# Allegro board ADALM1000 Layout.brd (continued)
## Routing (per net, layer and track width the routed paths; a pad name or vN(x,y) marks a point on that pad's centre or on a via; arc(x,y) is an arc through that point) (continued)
6V0: length 48.7
  TOP w0.254: C41.2 42.86,37.13 U8.8
  TOP w0.305: v1(74.96,13.85) 74.71,13.6 D10.2 ; 71.09,5.47 71.03,5.41 UB11.11 ; 66,32.57 C77.2 ; C77.2 66,33.74 ; C77.2 66.55,33.15 ; 45.88,50.17 45.62,50.43 U6.2 U6.1 ; C54.2 41.8,43 C76.1 v1(41.44,41.66) ; C54.2 42.83,42.46 ; C54.2 42.86,42.97 A3.8 ; C47.1 41.67,37.16 C41.2 ; U6.1 45.05,49.36 ; U6.1 46,49.93 ; D10.5 74.71,15.5 v1(74.46,15.76) ; R97.1 46.77,47.89 46.52,47.63 46.01,47.63
  TOP w0.33: UA11.11 68.94,40.85
  TOP w0.356: 46.68,17.28 46.56,17.15 B3.8
  TOP w0.381: D7.5 v1(74.96,39.12) ; D7.2 v1(74.96,42.81)
  TOP w0.508: v1(69.21,42.84) C68.1 C46.2 70.08,40.85 68.94,40.85 ; C47.1 41.44,36.15 ; v1(67.47,22.49) 66.46,22.49 ; 66.46,22.49 66.33,22.36 66.33,20.84 B4.8 ; 66.46,22.49 65.69,22.49 64.8,23.38 C82.1 64.3,23.06 v1(64.3,21.98) ; 66.07,32.24 A4.8 67.47,31.63 ; 45.74,47.89 C106.1 45.06,48.64 ; 46.68,17.28 47.2,17.8 C79.2 48.08,17.8 C80.1 v1(48.45,19.31) ; C41.2 v1(42.83,36.46) ; 71.09,5.47 71.79,5.47 71.79,6.9 C62.1 v1(71.12,7.28)
  TOP w0.635: 67.14,35.31 C78.1 66.37,34.33
  TOP w0.762: v1(48.42,51.7) v1(48.42,52.59) 48.66,52.34 D3.A
  vias: v1(41.44,35.95) v1(42.2,41.66) v1(42.2,35.95) v1(42.83,42.17) v1(46.01,48.52) v1(46.01,47.76) v1(65.95,34.04) v1(66.71,34.04)
6V5: length 33.1
  TOP w0.254: R18.1 27.97,33.03 28.61,32.39 32.93,32.39 33.69,33.15
  TOP w0.635: E4.1 39.79,45.79 39.79,33.79 39.15,33.15
  TOP w0.762: L4.2 38.19,39.25 ; L4.2 36.99,38.44 ; L4.2 34.83,39.25 C45.1
  TOP w1.016: C29.1 35.42,35.06 ; C29.1 C45.1 ; C29.1 34.32,33.41
-1V0: length 41.9
  TOP w0.305: v1(48.42,39.76) 48.42,39.25 48.59,39.08 U8.4 49.12,39.08 49.25,39.21 v1(49.25,39.76) ; 42.83,44.43 C54.1 41.8,43.88 C76.2 41.44,45.02 ; 64.58,33.15 C77.1 65.13,33.74 ; 63.22,40.96 63.34,40.85 UA11.2 65.88,40.85 UA11.PAD ; D10.1 v1(74.06,13.85) ; D10.4 v1(75.36,15.76) ; v1(49.25,45.6) 49.25,45.05 49.12,44.92 A3.4 48.59,44.92 48.42,45.09 v1(48.42,45.6) ; B3.4 v1(48.51,12.96) ; UB11.PAD 67.78,5.41 UB11.2 65.24,5.41 ; v1(62.65,27.82) A4.4
  TOP w0.356: D7.4 v1(74.31,40.71) 75.03,40.71 75.61,41.3 D7.1
  TOP w0.508: v1(67.47,23.5) 66.71,23.5 C81.1 ; v1(50.05,19.31) C80.2 ; R36.1 -3.38,40.99 ; R36.1 -4.28,41.84 ; R36.1 -5.19,40.99 ; v1(47.28,19.57) C79.1 ; 42.83,38.58 C41.1 42.14,38.04 41.65,38.53 C47.2 41.44,39.3 ; v1(65.19,7.75) 64.53,7.75 64.4,7.63 64.38,7.63 C93.1 64.04,5.47 64.1,5.41 65.24,5.41 ; C82.2 63.03,23.06 v1(63.03,21.98) ; v1(63.29,42.3) 62.58,42.3 C91.1 C90.2 63.22,40.96 ; v1(60.99,15.88) B4.4
  TOP w0.635: 64.77,34.33 C78.2 63.99,35.31
  vias: v1(-4.79,42.93) v1(-4.79,42.04) v1(-3.78,42.93) v1(-3.78,42.04) v1(41.44,45.22) v1(41.44,39.5) v1(42.2,45.22) v1(42.2,39.5) v1(42.83,44.71) v1(42.83,38.87) v1(64.23,34.04) v1(64.42,33.15) v1(65.06,34.04)
-1V0_U5: length 37.1
  TOP w0.254: CSS.1 2.57,44.58 4.61,44.58 U5.PAD
  TOP w0.305: 8.16,47.63 7.91,47.38 7.91,46.49 7.52,46.1 U5.12 6.12,46.1 U5.PAD
  TOP w0.508: RC1.1 3.27,51.71 ; RC1.1 2.52,51 ; RC1.1 3.27,50.29 ; L2.1 -0.7,39.83 ; L2.1 -0.7,38.41 ; L2.1 -1.45,39.12 ; CVCC.2 10.21,47.59 ; CVCC.2 9.31,48.45 ; CVCC.2 8.4,47.59 ; -1.54,41.03 RFILT.1 ; RFILT.1 -0.69,41.93 ; RFILT.1 -0.69,40.13 ; 8.35,51.75 RF2.1 9.06,51 ; -4.28,38.44 R36.2 ; R36.2 -3.38,39.29 ; R36.2 -5.19,39.29 ; -5.52,37.29 D1.A ; D1.A -4.16,36.35 ; D1.A -4.16,38.23 ; 0.29,47.81 RFREQ.1 ; RFREQ.1 0.29,49.23 ; RFREQ.1 -0.46,48.52 ; 3.34,48.51 CC2.1 ; CC2.1 3.34,49.93 ; CC2.1 2.59,49.22
  TOP w0.762: CSS.1 -0.85,45.35
  TOP w0.889: D1.A -2.8,37.29 -2.34,36.84 COUT2.N
GND: length 319.6
  TOP w0.254: U1.72 7.85,19.64 v1(7.53,19.31) ; U9.5 29.79,40.29 ; U9.5 29.36,41 ; U9.5 29.36,39.58 ; C2.1 7.35,3.71 U1.3 ; U1.61 13.35,19.68 ; U1.82 v1(5.88,15.96) ; U1.89 5.76,12.46 v1(6,12.71) ; U1.35 v1(18.83,11.46) ; 28.99,39.5 28.86,39.64 U9.4 28.86,41.29 U9.PAD
  TOP w0.305: D5.1 v1(23.97,3.8) ; 3.72,22.92 C7.2 3.72,24.34 ; v1(52.99,32.4) UA9.14 ; UA9.14 UA9.13 ; UA9.14 50.83,32.4 UA9.PAD ; v1(41.18,21.47) 41.06,21.6 40.04,21.6 39.78,21.86 U12.4 39.78,24.02 ; v1(56.68,51.82) 56.56,51.71 U7.3 54.64,51.71 54.52,51.58 ; 0.59,26.75 D9.1 ; D9.1 0.59,27.87 ; D9.1 v1(1.43,27.31) ; UB9.PAD 49.95,7.51 50.66,8.22 50.66,8.46 50.7,8.49 UB9.1 50.8,8.9 v1(51.34,8.9) ; UB9.PAD 50.19,7.25 UB9.14 52.23,7.25 52.36,7.38 v1(52.36,8.01) ; UB9.PAD 49.7,7.5 48.95,8.25 UB9.5 48.44,8.87 v1(48.42,8.9) ; D2.4 74.7,44.48 v1(74.46,44.72) ; UA9.13 52.98,31.9 ; UA9.13 52.08,31.27 ; C37.1 v1(9.05,24.52) ; 31.28,7.83 P3.5 ; P3.5 32.44,9 ; P3.5 31.28,10.17 ; RF1.2 v1(11.46,48.39) ; 30.84,41.66 C30.2 31.7,40.76 ; C11.1 v1(12.23,45.85) ; C112.1 51.85,53.06 ; C112.1 52.43,52.52 ; C112.1 51.27,52.52 ; U1.46 21.75,16.96 v1(22.2,17.41) ; C20.2 26.4,39.5 ; C20.2 24.98,39.5 ; C20.2 25.69,40.25 ; 39.78,24.02 40.28,23.52 U12.5 40.34,22.49 v1(40.93,22.49) ; 39.78,24.02 U12.PAD ; U11.6 30.5,23.52 ; 30.5,23.52 U11.5 31.6,22.55 31.91,22.23 v1(31.91,21.72) ; 30.5,23.52 30,24.02 ; 25.69,41.55 C109.1 26.4,42.3 ; UB11.3 65.37,4.76 v1(65.06,4.45) ; v1(52.8,49.09) 51.98,49.09 C107.2 51.72,49.09 v1(50.9,49.09) ; 24.29,41.55 R12.2 23.58,42.3 ; 13.65,27.25 P5.2 ; P5.2 14.26,28.33 ; P5.2 13.65,29.41 ; C38.1 26.45,29.73 v1(25.56,29.73) ; U12.6 41.57,23.52 41.97,23.12 v1(42.2,23.12) ; U10.3 52.37,24.14 53.32,24.14 53.63,24.45 v1(53.63,24.9) ; v1(53.12,8.9) 53.37,9.15 C70.2 ; v1(15.15,42.43) 15.66,42.94 U2.4 ; C69.2 51.8,41.1 C27.2 ; UA9.PAD 51.29,33.36 51.29,33.6 51.33,33.64 UA9.1 51.33,34.79 v1(51.6,35.06) ; UA9.PAD 49.87,33.36 49.62,33.36 49.59,33.4 UA9.5 49.08,33.89 49.07,33.9 v1(49.07,34.01) ; v1(41.31,26.17) 41.25,26.11 U12.10 41.23,25.53 40.42,25.53 39.4,24.52 U12.PAD ; v1(31.47,26.17) U11.10 30.5,25.52 U11.PAD ; R38.2 v1(42.71,46.49) ; v1(75.36,10.55) D11.4 ; 61.64,43.5 C91.2 ; C91.2 62.39,44.19 ; C91.2 63.14,43.5 ; R95.1 23.91,40.25 ; R95.1 24.62,39.5 ; R95.1 23.2,39.5 ; U11.PAD 29,24.02 U11.19 ; U11.PAD U11.8 v1(32.55,24.52) ; U11.PAD 29,25.02 U11.17 26.65,25.02 v1(26.51,25.15) ; U11.PAD 30,24.02 ; C23.2 26.58,45.64 ; R62.2 44.18,42.22 ; R62.2 44.18,40.53 C42.1 v1(43.34,40.52) ; R62.2 43.63,41.66 ; D8.1 0.59,26.6 ; D8.1 0.59,25.48 ; D8.1 v1(1.43,26.04) ; 13.65,29.79 P6.2 13.65,31.95 ; U3.PAD -5.05,14.1 -4.65,13.71 U3.3 -4.65,12.31 ; v1(35.98,25.15) 36.11,25.02 U12.17 ; D5.4 v1(22.15,5.1) ; v1(17.74,2.86) C19.1 ; 7.78,22.92 C6.2 7.78,24.34 ; v1(11.33,2.89) C4.1 ; 7.15,34.36 L1.2 ; U6.PAD 43.35,50.93 U6.6 ; D11.1 74.06,10.31 v1(73.95,10.42) ; C96.2 v1(46.39,33.15) ; U12.8 v1(42.22,24.52) ; 48.22,49.74 R98.2 47.66,49.2 ; v1(43.34,21.85) 43.34,20.96 C99.1 ; 60.66,52.64 C8.1 61.83,52.64 ; 30,24.02 U11.4 30,21.86 30.2,21.66 31.09,21.66 v1(31.15,21.72) ; U12.19 37.31,24.01 38.52,24.01 39.02,24.52 U12.PAD ; C63.1 v1(46.52,25.28) ; 1.43,30.87 v1(1.56,31) ; C94.1 v1(45.5,30.87) ; D6.4 v1(23.78,8.15) ; D2.1 v1(76,44.71) ; UA11.3 v1(63.15,40.19) ; v1(17.37,23.25) 17.18,23.44 16.73,23.44 C36.1 ; 13.65,24.71 P4.2 ; P4.2 14.26,25.79 ; P4.2 v1(13.65,27.06) ; v1(52.05,39.5) 51.85,39.31 R22.2 ; D6.1 v1(24.04,6.85) ; U2.8 v1(16.16,40.9)
  TOP w0.356: UA11.13 67.18,43.08 67.6,43.5 v1(67.6,43.57) ; UB11.13 69.08,7.33 69.63,7.88 v1(69.63,8.14)
  TOP w0.381: C61.1 24.25,23.63 C59.2 24,23.88 v1(22.98,23.88) ; 34.2,22.23 v1(33.18,22.23)
  TOP w0.406: C48.1 13.43,23.63 v1(12.86,23.63) ; P1.5 -2.98,28.36 v1(-2.63,28.01) ; v1(7.97,3.44) 7.46,3.44 C2.1 ; v1(-2.63,28.01) -2.94,27.71 P1.4 ; v1(-2.63,28.01) -1.81,28.01 -1.62,28.2 v1(-0.22,28.2) ; v1(15.27,23.31) 15.15,23.44 14.63,23.44 C35.1 ; v1(52.05,39.5) C49.1 ; v1(52.05,42.08) C69.2
  TOP w0.508: 0.67,9.71 C53.1 ; C53.1 0.67,11.13 ; C53.1 v1(-0.35,10.42) ; 2.56,36.49 COUT1.1 ; COUT1.1 3.46,35.64 ; COUT1.1 4.37,36.49 ; C55.2 v1(47.41,2.8) ; R8.2 50.03,16.61 v1(49.22,16.61) ; 70.27,45.4 C68.2 69.36,44.55 ; 0.67,12.94 C50.1 v1(-0.35,13.72) ; -4.16,16.31 C9.1 ; C9.1 -3.41,17.03 ; C9.1 -4.16,17.74 ; C13.1 59.69,48.14 ; C13.1 59.15,48.72 ; C13.1 59.15,47.56 ; R40.2 v1(54.26,12.2) ; 53.31,44.84 53.31,45.78 ; 53.31,44.84 53.97,44.84 ; 53.31,44.84 53.31,43.9 ; 45.12,26.09 C64.1 46.1,25.32 ; C62.2 v1(71.12,8.99) ; v1(-3.14,17.53) -3.14,18.38 C12.2 ; v1(24.55,10.93) 24.55,11.44 C32.1 ; C5.1 v1(-1.24,19.06) ; -5.52,33.33 -4.16,33.33 ; -4.16,33.33 -2.8,33.33 ; -4.16,33.33 -4.16,34.27 ; -4.16,33.33 v1(-4.16,32.01) ; 53.3,4.07 C71.1 ; C71.1 54.72,4.07 ; C71.1 54.01,3.32 ; C33.1 19.08,24.74 ; C33.1 19.67,24.19 ; C33.1 18.5,24.19 ; v1(70.9,3.56) 71.54,4.2 C58.1 ; P2.4 75.24,28.96 ; P2.4 74.08,30.13 ; P2.4 74.08,27.79 ; v1(63.05,6.36) UB12.2 ; R55.1 0.29,31.58 ; R55.1 0.29,30.16 ; R55.1 1.43,30.87 ; C51.1 v1(-1.24,16.26) ; C75.1 40.88,19.44 ; C75.1 40.17,18.69 ; C75.1 39.45,19.44 ; 49.31,27.07 C65.2 ; C65.2 50.02,27.82 ; C65.2 48.6,27.82 ; 0.29,28.51 C101.1 ; C101.1 v1(1.56,29.22) ; C101.1 0.29,29.93 ; 38.13,17.66 C73.1 ; C73.1 37.03,18.61 ; C73.1 39.24,18.61 ; 50.96,27.07 C66.1 ; C66.1 51.67,27.82 ; C66.1 50.25,27.82 ; v1(7.15,33.41) 7.15,34.36 ; P2.5 75.24,26.42 ; P2.5 74.08,27.59 ; P2.5 74.08,25.25 ; -4.07,10.43 C15.2 -4.07,8.63 ; 36.81,28.53 C21.1 36.81,27.36 ; C52.1 0.67,12.78 ; C52.1 0.67,11.36 ; C52.1 v1(-0.35,12.07) ; v1(53.69,17.28) C97.2 ; 44.51,3.7 R27.2 ; R27.2 v1(43.6,4.45) ; R27.2 45.22,4.45 ; 64.79,51.82 C10.2 64.11,52.57 ; C95.1 v1(52.81,20.71) ; v1(66.71,13.98) 66.71,14.74 C31.2 ; v1(25.56,20.2) 25.69,20.33 C72.1 26.89,19.25 ; 5.57,34.58 L1.2 ; L1.2 8.72,34.58 ; L1.2 7.15,35.33 ; C34.1 25.23,16.9 ; C34.1 24.48,17.61 ; C34.1 24.48,16.19 ; C44.1 v1(62.26,26.93) ; 54.83,47.9 C108.2 ; C108.2 54.83,49.4 ; C108.2 54.15,48.65 ; 58.15,52.31 U4.3 ; U4.3 59.78,52.31 ; U4.3 58.96,51.3 ; C92.1 64.3,4.45 v1(65.06,4.45) ; C24.1 24.1,9.72 v1(24.94,9.72) ; R3.1 v1(-1.24,17.66) ; 33.98,19.55 C22.2 ; C22.2 33.98,21.36 ; C22.2 33.13,20.45 ; 42.97,47.89 C106.2 43.66,48.64 ; 7.4,39.25 CIN1.2 ; CIN1.2 6.29,40.2 ; CIN1.2 8.51,40.2 ; 42.64,18.6 B2.3 41.98,17.66 ; 0.45,5.91 C1.2 ; C1.2 v1(2.89,5.91) ; C1.2 1.56,4.96 ; v1(58.2,40.01) 58.45,40.27 UA12.2 ; C40.1 v1(62.01,13.72) ; C14.1 v1(-3.14,11.31) ; C14.1 -4.28,12.02 ; C14.1 -4.28,10.6 ; C74.1 32.79,20.71 ; C74.1 32.04,21.42 ; C74.1 32.04,20 ; 54.01,9.9 C70.2 54.72,9.15 ; C46.1 v1(69.38,39.76) ; C93.2 v1(65.19,8.99) ; C56.1 v1(51.09,2.8) ; -1.12,33.79 COUT2.P 0.29,32.47 ; 45.8,52.52 C105.1 46.97,52.52 ; v1(63.15,40.19) 63.04,40.08 C90.1 ; v1(45.35,7.88) C26.1
  TOP w0.635: R40.2 51.94,12.2 C28.2 51.7,12.39 50.9,12.39 v1(50.58,12.07) ; 20.26,25.06 C3.2 ; C3.2 21.24,25.84 ; C3.2 22.22,25.06 ; v1(54.52,49.66) U7.PAD v1(54.52,52.39) ; R17.2 v1(66.71,25.03)
  TOP w0.762: 21.1,41.83 C17.2 ; C17.2 22.91,41.83 ; C17.2 22.01,40.98 ; v1(38.55,48.65) C104.2 v1(37.37,50.05) ; U6.PAD v1(43.6,48.9) ; COUT2.P v1(2.19,33.79) ; C18.1 20.7,41.73 ; C18.1 19.59,40.77 ; C18.1 18.49,41.73
  TOP w1.016: 30.44,35.06 C29.2 ; C29.2 C45.2 ; C29.2 31.53,33.41 ; C45.2 31.53,40.39 ; C45.2 30.44,38.74 ; C15.2 v1(-2.89,9.53)
  BOTTOM w0.508: JTAG.3 15.27,31.25 15.53,31.5 16.54,31.5 ; 16.54,31.5 v1(18.2,31.5) v1(19.08,31.5) JTAG.9 ; 16.54,31.5 JTAG.5
  vias: v1(-4.04,12.33) v1(-3.14,16.39) v1(0.16,32.14) v1(1.18,32.14) v1(1.56,29.98) v1(2.19,32.9) v1(2.19,32.14) v1(3.08,28.71) v1(3.08,23.63) v1(3.46,35.31) v1(3.59,22.11) v1(5.11,33.28) v1(5.11,28.71) v1(6.26,39) v1(7.02,39) v1(7.53,24.52) v1(7.78,39) v1(9.05,25.79) v1(11.08,36.08) v1(13.12,29.6) v1(13.12,19.31) v1(18.77,16.26) v1(19.21,40.52) v1(19.21,39.63) v1(19.21,38.62) v1(19.97,25.53) v1(19.97,24.77) v1(20.23,40.52) v1(20.23,39.63) v1(20.23,38.62) v1(21.24,40.65) v1(21.24,39.63) v1(21.24,38.62) v1(21.24,37.6) v1(21.24,36.58) v1(21.24,35.57) v1(22.07,29.03) v1(22.26,40.65) v1(22.26,39.63) v1(22.26,38.62) v1(22.26,37.6) v1(22.26,36.58) v1(22.26,35.57) v1(24.04,17.91) v1(25.94,41.09) v1(26.07,46.74) v1(26.51,40.58) v1(26.64,42.23) v1(26.64,41.47) v1(26.83,46.74) v1(29.24,39.12) v1(29.24,37.22) v1(30.01,39.12) v1(30.01,37.22) v1(31.91,19.69) v1(33.94,19.18) v1(36.86,27.06) v1(39.66,18.3) v1(41.18,19.18) v1(42.07,19.18) v1(42.71,47.89) v1(42.96,26.3) v1(45.5,52.59) v1(47.28,52.59) v1(47.53,29.09) v1(47.66,48.9) v1(48.42,27.82) v1(48.8,31) v1(51.02,52.46) v1(51.98,27.82) v1(52.68,52.46) v1(52.99,31.5) v1(52.99,4.2) v1(53.25,46.11) v1(54.26,44.84) v1(57.95,52.33) v1(59.22,47.25) v1(59.98,52.33) v1(60.74,44.33) v1(61.5,45.09) v1(61.49,43.44) v1(62.14,52.84) v1(62.39,44.34) v1(63.29,43.44) v1(64.04,52.84) v1(65.06,51.82) v1(69.21,44.2)
VCC: length 6
  TOP w0.305: 8.16,45.6 U5.11
  TOP w0.508: CVCC2.1 v1(-1.74,43.31) ; v1(10.7,45.98) 10.61,45.89 CVCC.1 9.01,45.6 8.16,45.6 ; v1(-2.38,46.62) R21.2
CHA: length 62.6
  TOP w0.305: UA11.9 v1(68.18,38.74) ; v1(64.55,38.74) 64.23,39.07 UA11.4
  TOP w0.381: 76.11,39.25 75.61,39.74 D7.6 75.84,40.18
  TOP w0.508: A2.4 53.31,47.25 53.56,47 54.14,47 55.15,45.98 63.03,45.98 R48.2 R28.2 ; 76.11,39.25 76.11,36.08 P2.2 ; v1(68.18,38.74) 68.43,38.49 70.77,38.49 71.54,39.25 71.54,45.35 69.38,47.51 68.49,47.51 R28.2 ; R28.2 68.36,48.65 70.14,48.65 71.03,47.76 75.6,47.76 78.52,44.84 78.52,41.28 77.89,40.65 77.59,40.65 R70.1 77.12,40.18 75.84,40.18
  BOTTOM w0.508: v1(64.55,38.74) v1(68.18,38.74)
CHA_2V5: length 63.3
  TOP w0.254: UA11.16 65.23,42.77 64.93,43.06 v1(64.93,43.57)
  TOP w0.33: UB11.16 67.13,7.71 v1(66.71,8.14)
  TOP w0.508: C102.2 71.79,28.84 R39.2 70.23,30.89 R57.2 ; R57.2 73.82,31.25 P2.3 75.73,31.5 77.5,29.73 v1(77.5,18.8) ; R57.2 R49.2 70.58,34.81 70.07,35.31 v1(69.5,35.31)
  BOTTOM w0.508: v1(66.71,8.14) 69.88,11.31 75.98,11.31 77.5,12.83 v1(77.5,18.8) ; v1(64.93,43.57) 64.93,44.08 65.44,44.58 67.85,44.58 68.5,43.94 68.5,42.29 70.14,40.65 70.14,39.12 69.5,38.49 v1(69.5,35.31)
CHA_IN: length 16.9
  TOP w0.406: 73.77,41.23 74.07,41.54 74.08,41.54 74.31,41.78 D7.3 74.31,42.02 73.99,42.34
  TOP w0.508: 73.99,42.34 72.93,43.4 R71.1 72.42,42.97 72.42,38.74 70.65,36.96 69.97,36.96 R29.2 ; 73.77,41.23 73.31,40.77 73.31,37.35 P2.1
CHB: length 66.7
  TOP w0.356: UB11.9 70.01,4.04 v1(70.01,3.18) ; v1(65.18,3.56) 65.73,4.11 UB11.4
  TOP w0.406: 73.82,14.61 74.06,14.85 D10.6 74.06,15.14 73.57,15.63
  TOP w0.508: 73.82,14.61 73.61,14.61 R67.1 70.35,13.18 R63.2 ; R63.2 71.03,11.06 71.03,10.55 71.39,10.19 73.04,10.19 73.31,9.91 73.31,6.23 72.81,5.72 72.81,3.31 72.3,2.8 70.39,2.8 v1(70.01,3.18) ; R63.2 R64.2 v1(64.93,12.45) ; 42.64,15.12 42.64,13.91 43.47,13.09 v1(43.47,11.95) ; 73.57,15.63 73.44,15.76 73.44,17.41 72.55,18.3 72.55,19.82 P2.7
  BOTTOM w0.508: v1(70.01,3.18) 69.25,3.94 65.57,3.94 v1(65.18,3.56) ; v1(43.47,11.95) 44.87,10.55 54.64,10.55 56.55,12.45 v1(64.93,12.45)
CHB_5V: length 11.2
  TOP w0.508: P2.6 72.11,23.88 R66.2 R65.2 70.71,19.82 70.35,19.46 R33.2 71.41,17.53 C57.2
CHB_IN: length 17.2
  TOP w0.406: 75.81,12.58 D10.3 75.36,13.1 75.72,13.47
  TOP w0.508: R31.2 74.88,8.14 77.25,8.14 78.39,9.28 78.39,11.28 77.99,11.69 77.47,11.69 R68.1 76.58,12.58 75.81,12.58 ; 75.72,13.47 76.23,13.98 76.23,16.64 P2.8
CLR_N: length 57.4
  TOP w0.254: U1.12 11.85,6.22 10.83,7.25 10.83,10.17 v1(11.59,10.93) ; U10.5 v1(52.37,25.81)
  BOTTOM w0.254: v1(11.59,10.93) 11.59,11.95 12.99,13.34 16.35,13.34 17.18,14.17 19.08,14.17 21.37,16.45 21.37,17.47 22.58,18.68 29.88,18.68 30.64,17.91 36.74,17.91 37.82,18.99 40.17,18.99 40.93,18.23 42.01,18.23 43.34,19.57 43.85,19.57 47.46,23.17 51.14,23.17 52.37,24.4 v1(52.37,25.81)
CNV1: length 53.9
  TOP w0.254: v1(40.8,30.61) 40.8,28.33 40.28,27.8 U12.11 ; U1.86 6.81,13.96 7.78,14.93 7.78,16.52 9.18,17.91 12.92,17.91 13.43,17.41 v1(16.8,17.41) ; U11.11 30.5,26.92 30.64,27.06 32.55,27.06 v1(33.69,28.2)
  BOTTOM w0.254: v1(40.8,30.61) 40.17,31.25 35.98,31.25 33.69,28.96 v1(33.69,28.2) 31.66,28.2 27.53,24.07 24.23,24.07 18.89,18.74 18.13,18.74 v1(16.8,17.41)
D+: length 15.4
  TOP w0.254: U1.76 4.59,18.97 3.76,18.97 3.08,19.65 3.08,21.17 2.28,21.98 1.39,21.98 R4.2 0.03,23.34 0.03,26.8 -0.47,27.31 D9.2 -0.85,26.99 -2.87,26.99 -2.94,27.06 P1.3
D+_A: length 17.5
  TOP w0.254: R4.1 0.83,20.84 0.16,20.84 -0.47,21.47 -2.12,21.47 -2.38,21.22 -2.38,15.67 -1.45,14.74 1.94,14.74 3.66,16.46 U1.81
D-: length 16.6
  TOP w0.254: P1.2 -3.07,26.41 -3,26.48 -0.96,26.48 D8.2 -0.47,25.99 -0.47,23.12 -1.27,22.32 R5.2 -1.02,21.98 -0.22,21.98 0.29,21.47 2.07,21.47 2.57,20.96 2.57,19.44 3.55,18.46 U1.77
D-_A: length 12.4
  TOP w0.254: U1.80 4.59,16.97 3.45,16.97 1.73,15.25 -1.24,15.25 -1.87,15.88 -1.87,20.11 R5.1
FB: length 4.2
  TOP w0.254: U9.2 27.85,39.58 27.59,39.31 27.59,38.49 R19.2 R18.2
ISENSE-A: length 13.1
  TOP w0.254: 50.33,40.21 50.33,41.66 50.64,41.97 C27.1 51.6,42.48 51.6,42.75 R15.2 ; 50.33,40.21 50.33,38.76 50,38.43 ; 50.33,40.21 R22.1 ; 50,38.43 50.71,37.73 50.71,35.57 50.58,35.44 50.58,35.06 ; 50,38.43 U8.3 ; 50.58,35.06 50.33,34.81 UA9.3 ; 50.58,35.06 50.83,34.81 UA9.2
ISENSE-A_BUF: length 31.5
  TOP w0.254: R86.1 v1(34.45,23.76) ; v1(44.42,26.3) 43.77,25.65 R92.1 ; 50.2,37.09 50.16,37.13 U8.1 ; 50.2,37.09 50.2,35.95 v1(49.69,35.44) ; 50.2,37.09 50.2,37.47 49.89,37.78 U8.2
  BOTTOM w0.254: v1(34.45,23.76) 43.98,23.76 44.42,24.2 v1(44.42,26.3) 44.42,30.68 45.63,31.88 45.63,33.54 47.15,35.06 48.93,35.06 49.31,35.44 v1(49.69,35.44)
ISENSE-B: length 46.5
  TOP w0.254: UB9.2 50.19,9.91 50.2,9.91 49.7,9.91 ; v1(43.34,23.12) 42.58,22.36 42.58,20.07 43.09,19.57 44.23,19.57 45.31,18.49 45.31,15.44 46.64,14.1 48.93,14.1 49.7,13.34 49.7,9.91 ; 49.7,9.91 UB9.3 ; v1(45.12,29.34) 43.98,30.49 43.98,35.31 44.61,35.95 45.37,35.95 46.01,36.58 46.01,38.62 45.54,39.08 U8.5
  TOP w0.305: R16.2 R40.1 51.94,10.93 C28.1 50.92,9.91 50.2,9.91
  BOTTOM w0.254: v1(45.12,29.34) 45.12,23.82 44.42,23.12 v1(43.34,23.12)
ISENSE-B_BUF: length 28.8
  TOP w0.254: U8.7 45.33,37.78 ; 45.33,37.78 45.5,37.62 45.5,36.84 45.12,36.46 44.36,36.46 43.47,35.57 43.47,29.6 v1(43.72,29.34) ; 45.33,37.78 45.5,37.95 45.5,38.23 45.3,38.43 U8.6 ; R88.1 v1(43.77,24.72) ; R90.1 v1(34.45,25.28)
  BOTTOM w0.254: v1(34.45,25.28) 35.09,25.92 40.55,25.92 41.25,25.22 42.71,25.22 43.2,24.72 v1(43.77,24.72) 43.77,26.54 43.79,26.56 43.79,29.28 v1(43.72,29.34)
LDAC_N: length 55.9
  TOP w0.254: U10.4 51.37,24.64 51.11,24.89 v1(51.11,24.9) ; U1.6 8.85,6.54 9.56,7.25 9.56,10.93 v1(11.15,12.52)
  BOTTOM w0.254: v1(11.15,12.52) 12.54,13.91 15.97,13.91 16.73,14.68 18.83,14.68 20.86,16.71 20.86,17.65 22.33,19.12 30.06,19.12 30.76,18.42 36.48,18.42 38.2,20.14 43.66,20.14 47.28,23.76 49.97,23.76 v1(51.11,24.9)
NRST: length 9.2
  TOP w0.254: v1(15.35,19.44) U1.57
  BOTTOM w0.254: JTAG.10 19.08,23.38 18.7,22.99 18.7,21.72 17.75,20.77 16.69,20.77 v1(15.35,19.44)
OVC_FAULT: length 23.8
  TOP w0.254: U1.67 10.35,21.81 10.19,21.97 10.19,32.14 12.1,34.04 14.89,34.04 16.29,35.44 16.29,37.73 16.72,38.16 R93.2 17.18,39.6 U2.10
PA0: length 27
  TOP w0.254: v1(19.27,3.18) 19.66,3.56 22.15,3.56 22.39,3.8 ; 22.39,3.8 21.37,4.82 21.37,6.48 20.89,6.96 U1.26 ; 22.39,3.8 D5.6 ; R41.2 2.19,3.69 v1(2.64,4.13)
  BOTTOM w0.254: v1(2.64,4.13) 14.39,4.13 14.77,3.75 18.7,3.75 v1(19.27,3.18)
PA1: length 22.1
  TOP w0.254: R42.2 15.15,3.69 16.57,2.27 19.23,2.27 20.02,3.06 25.56,3.06 26.45,3.94 26.45,4.71 26.05,5.1 D5.3 24.02,5.1 23.4,5.72 22.89,5.72 21.16,7.46 U1.27
PA2: length 36.4
  TOP w0.254: R43.2 4.66,4.82 v1(4.67,4.83) ; v1(20.23,2.17) 20.99,1.4 24.8,1.4 27.09,3.69 27.09,5.09 26.45,5.72 24.16,5.72 23.04,6.85 D6.6 22.53,6.85 21.42,7.96 U1.28
  BOTTOM w0.254: v1(20.23,2.17) 20.23,3.63 19.59,4.26 15.02,4.26 14.45,4.83 v1(4.67,4.83)
PA3: length 32.2
  TOP w0.254: U1.29 21.31,8.46 21.62,8.77 24.24,8.77 D6.3 25.8,8.15 30.77,3.18 34.58,3.18 35.09,3.69 35.09,10.04 34.07,11.06 34.07,14.1 34.83,14.87 34.83,16.39 34.58,16.64 R53.2
PA4: length 26.9
  TOP w0.254: v1(21.37,9.98) 21.37,9.28 21.05,8.96 U1.30 ; v1(40.17,15.63) 40.17,14.36 39.91,14.1 R14.1
  BOTTOM w0.254: v1(40.17,15.63) 37.5,15.63 35.47,13.6 34.77,13.6 34.26,14.1 24.55,14.1 21.37,10.93 v1(21.37,9.98)
PA5: length 26.5
  TOP w0.254: v1(17.18,10.74) 17.18,9.91 17.63,9.46 U1.31 ; v1(35.47,15.12) 35.47,16.26 35.85,16.64 R23.1
  BOTTOM w0.254: v1(17.18,10.74) 19.72,10.74 24.1,15.12 v1(35.47,15.12)
PA6: length 22.6
  TOP w0.254: U1.32 18.51,9.96 v1(17.88,10.1) ; R35.1 v1(35.09,14.23)
  BOTTOM w0.254: v1(17.88,10.1) 19.85,10.1 24.35,14.61 34.71,14.61 v1(35.09,14.23)
PA7: length 19.2
  TOP w0.254: v1(17.88,11.44) 18.85,10.46 U1.33 ; v1(30.9,15.76) 30.9,16.26 31.28,16.64 R44.1
  BOTTOM w0.254: v1(17.88,11.44) 18.58,12.14 20.35,12.14 23.85,15.63 30.01,15.63 30.13,15.76 v1(30.9,15.76)
PA28: length 51.7
  TOP w0.254: R50.2 42.39,13.09 42.77,12.71 42.77,7.82 42.26,7.31 v1(41.37,7.31) ; v1(5.88,15.18) 5.65,14.96 U1.84
  BOTTOM w0.254: v1(41.37,7.31) 40.67,6.61 27.72,6.61 26.7,5.6 23.47,5.6 22.26,6.8 16.52,6.8 15.95,7.37 9.56,7.37 6.83,10.1 6.83,14.23 v1(5.88,15.18)
PA29: length 55.2
  TOP w0.254: v1(40.1,7.69) 40.1,10.04 39.09,11.06 39.09,14.23 39.47,14.61 39.47,16.3 39.12,16.64 R52.2 ; U1.85 6.42,14.46 7.15,15.18 v1(7.15,16.14)
  BOTTOM w0.254: v1(40.1,7.69) 39.53,7.12 27.51,7.12 26.49,6.1 23.77,6.1 22.56,7.31 16.73,7.31 16.16,7.88 9.94,7.88 7.4,10.42 7.4,15.25 7.15,15.5 v1(7.15,16.14)
PB15: length 35.3
  TOP w0.254: U1.16 13.85,6.38 13.24,6.99 v1(13.24,8.52) ; v1(37.63,7.94) 37.63,10.61 37.82,10.8 37.82,12.9 37.63,13.09 R51.2
  BOTTOM w0.254: v1(37.63,7.94) 37.31,7.63 27.3,7.63 26.6,8.33 24.48,8.33 24.07,8.73 23.37,8.73 22.45,7.82 16.93,7.82 16.23,8.52 v1(13.24,8.52)
PWR_ENABLE: length 27
  TOP w0.254: U2.3 16.16,42.43 14.59,40.85 14.59,36.91 14,36.33 14,35.06 13.62,34.68 11.97,34.68 9.69,32.39 9.69,21.85 9.85,21.68 U1.68
RX1: length 35
  TOP w0.254: U1.20 15.85,6.67 15.02,7.5 15.02,14.1 14.13,14.99 14.13,15.95 v1(13.31,16.77) ; v1(27.59,29.73) R80.2
  BOTTOM w0.254: v1(13.31,16.77) 14.26,17.72 14.64,17.72 17.12,20.2 18.07,20.2 20.99,23.12 20.99,25.98 24.1,29.09 26.96,29.09 v1(27.59,29.73)
RX2: length 38.4
  TOP w0.254: v1(15.97,15.31) 15.53,14.87 15.53,7.63 16.35,6.8 U1.21 ; v1(36.99,29.77) R83.2
  BOTTOM w0.254: v1(36.99,29.77) 34.28,27.06 33.44,27.06 31.91,25.53 30.51,25.53 27.34,22.36 24.1,22.36 19.34,17.6 18.89,17.6 17.31,16.01 16.67,16.01 v1(15.97,15.31)
SCK: length 2.5
  TOP w0.254: R79.2 30.51,28.46 29.5,27.44 U11.13
SCK0: length 50.8
  TOP w0.254: v1(13.88,12.14) 13.18,11.44 13.18,10.23 12.48,9.53 12.48,6.99 12.85,6.62 U1.14 ; R72.1 v1(51.22,22.49)
  BOTTOM w0.254: v1(13.88,12.14) 16.67,12.14 17.69,13.15 19.59,13.15 23.15,16.71 29.56,16.71 29.75,16.9 43.47,16.9 45.25,18.68 45.25,19.37 47.72,21.85 50.58,21.85 v1(51.22,22.49)
SCK1: length 37.9
  TOP w0.254: U1.23 17.35,6.56 16.04,7.88 16.04,12.71 17.05,13.72 17.05,16.07 16.35,16.77 v1(14.45,16.77) ; v1(29.63,29.73) R79.1
  BOTTOM w0.254: v1(29.63,29.73) 28.74,29.73 27.59,28.58 24.35,28.58 21.5,25.72 21.5,22.93 18.32,19.76 17.43,19.76 v1(14.45,16.77)
SCK2: length 40.4
  TOP w0.254: v1(17.94,15.31) 17.94,13.79 16.54,12.39 16.54,8.14 17.85,6.83 U1.24 ; R82.1 v1(39.02,30.61)
  BOTTOM w0.254: v1(39.02,30.61) 38.39,30.61 37.88,30.11 37.88,29.47 34.96,26.55 33.69,26.55 32.17,25.03 30.77,25.03 27.59,21.85 24.29,21.85 20.35,17.91 20.35,16.96 18.7,15.31 v1(17.94,15.31)
SCL: length 127.9
  TOP w0.254: UB9.11 50.19,5.35 v1(50.45,5.09) ; v1(14.64,35.06) 14.64,36.2 15.16,36.73 U2.6 ; v1(58.07,11.69) 54.39,15.37 54.39,25.15 52.74,26.8 52.74,29.47 52.23,29.98 51.41,29.98 50.83,30.56 UA9.11 ; v1(26.96,12.39) 26.96,13.14 R2.2 26.97,13.26 26.45,13.79 21.56,13.79 21.24,13.46 U1.39
  BOTTOM w0.254: v1(14.64,35.06) 13.37,35.06 12.61,34.3 10.96,34.3 6.51,29.85 6.51,27.69 5.62,26.8 5.62,23.95 9.5,20.07 9.5,12.07 11.27,10.29 16.54,10.29 17.5,9.34 21.62,9.34 22.96,10.67 22.96,11.44 24.58,13.06 26.29,13.06 v1(26.96,12.39) 28.04,13.47 29.18,13.47 29.19,13.48 30.68,13.48 31.71,12.45 38.3,12.45 39.76,13.91 41.58,13.91 42.83,12.66 42.83,11.56 44.87,9.53 46.01,9.53 v1(50.45,5.09) 50.83,5.47 50.83,6.36 51.6,7.12 53.5,7.12 v1(58.07,11.69)
SDA: length 132.3
  TOP w0.254: UB9.12 50.7,5.77 50.95,5.52 51.9,5.52 v1(52.49,6.1) ; UA9.12 51.33,30.75 51.6,30.49 52.49,30.49 53.25,29.73 53.25,27.06 54.9,25.41 54.9,15.88 v1(59.09,11.69) ; U2.7 15.66,36.58 v1(15.66,36.08) ; v1(25.18,12.39) 25.18,13.14 R1.2 21.69,13.15 21.5,12.96 U1.38
  BOTTOM w0.254: v1(59.09,11.69) 53.88,6.48 52.87,6.48 v1(52.49,6.1) 50.83,4.45 47.91,4.45 47.02,5.34 47.02,7.69 45.82,8.9 44.74,8.9 42.33,11.31 42.33,12.45 41.37,13.41 39.98,13.41 38.52,11.95 30.9,11.95 30.29,12.55 28.96,12.55 27.97,11.56 26.01,11.56 v1(25.18,12.39) 24.8,12.01 24.8,11.69 25.24,11.25 25.24,10.68 24.91,10.34 23.39,10.34 21.88,8.83 17.31,8.83 16.42,9.72 10.96,9.72 8.86,11.82 8.86,19.82 4.99,23.69 4.99,27.06 5.88,27.95 5.88,30.11 10.7,34.93 12.48,34.93 13.62,36.08 v1(15.66,36.08)
SWMODE-A: length 60.6
  TOP w0.254: v1(49.69,40.9) 49.69,41.66 51.09,43.06 51.09,43.57 51.41,43.89 51.41,44.84 ; v1(17.18,35.06) 15.53,33.41 12.23,33.41 10.7,31.88 10.7,22.09 10.85,21.94 U1.66
  BOTTOM w0.254: v1(17.18,35.06) 17.94,34.3 41.56,34.3 45.88,38.62 49.18,38.62 50.07,39.5 50.07,40.52 v1(49.69,40.9)
SWMODE-B: length 57.5
  TOP w0.254: v1(40.8,12.64) 40.8,15.44 41.75,16.39 44.23,16.39 44.55,16.71 B2.1 ; U1.65 11.35,19.58 10.38,18.61 8.1,18.61 v1(7.15,17.66)
  BOTTOM w0.254: v1(7.15,17.66) 8.13,16.68 8.13,10.45 9.43,9.15 16.29,9.15 17.12,8.33 22.13,8.33 23.21,9.41 24.16,9.41 24.61,8.96 26.89,8.96 28.48,10.55 38.13,10.55 40.23,12.64 v1(40.8,12.64)
SYNC_N: length 54.5
  TOP w0.254: U1.13 12.35,6.48 11.59,7.25 11.59,9.66 12.54,10.61 12.54,11.82 v1(12.86,12.14) ; v1(50.33,22.49) 50.05,22.77 50.05,24.67 49.58,25.14 U10.6
  BOTTOM w0.254: v1(12.86,12.14) 13.5,12.77 16.61,12.77 17.5,13.66 19.34,13.66 22.89,17.22 29.31,17.22 29.5,17.41 43.28,17.41 44.67,18.8 44.67,19.57 47.6,22.49 v1(50.33,22.49)
TCK: length 4.8
  TOP w0.254: v1(15.85,21.91) U1.56
  BOTTOM w0.254: JTAG.4 15.27,24.2 15.97,23.5 15.97,22.49 15.85,22.37 v1(15.85,21.91)
TDI: length 15.9
  TOP w0.254: v1(14.07,18.49) 14.39,18.17 16.93,18.17 18.35,19.6 U1.51
  BOTTOM w0.254: v1(14.07,18.49) 14.7,19.12 14.7,20.71 15.27,21.28 17.43,21.28 18.2,22.04 18.2,23.63 17.81,24.01 JTAG.8
TDO: length 4.6
  TOP w0.254: v1(16.67,21.91) 16.85,21.73 U1.54
  BOTTOM w0.254: v1(16.67,21.91) 16.67,22.36 16.54,22.49 JTAG.6
TMS: length 9.8
  TOP w0.254: U1.55 16.35,19.37 15.78,18.8 14.77,18.8 v1(14.07,19.5)
  BOTTOM w0.254: v1(14.07,19.5) 14.07,25.09 JTAG.2
TX0: length 44.3
  TOP w0.254: v1(45.88,18.61) 45.88,20.2 46.9,21.22 R73.1 ; U1.17 14.35,6.77 13.88,7.25 v1(13.88,10.93)
  BOTTOM w0.254: v1(45.88,18.61) 43.66,16.39 30.01,16.39 29.82,16.2 23.4,16.2 19.91,12.71 18,12.71 16.93,11.63 14.58,11.63 v1(13.88,10.93)
TX1: length 38
  TOP w0.254: v1(13.3,15.31) 13.3,14.81 14.51,13.6 14.51,7.37 15.35,6.53 U1.19 ; R78.1 v1(31.68,29.73)
  BOTTOM w0.254: v1(31.68,29.73) 31.15,29.73 29.5,28.07 24.61,28.07 22.07,25.53 22.07,22.8 18.45,19.18 17.62,19.18 15.5,17.06 15.5,16.61 14.96,16.07 14.06,16.07 v1(13.3,15.31)
TX2: length 47.2
  TOP w0.254: v1(36.99,30.61) 37.63,31.25 39.4,31.25 40.04,30.61 R81.1 ; v1(11.15,13.53) 8.92,11.31 8.92,7.37 8.35,6.8 U1.5
  BOTTOM w0.254: v1(36.99,30.61) 36.36,30.61 34.45,28.71 34.45,28.07 33.94,27.57 31.78,27.57 27.85,23.63 24.67,23.63 19.27,18.23 18.51,18.23 16.99,16.71 16.42,16.71 14.39,14.68 12.29,14.68 v1(11.15,13.53)
UA11-IN0: length 87.7
  TOP w0.254: v1(10.19,16.71) 8.99,16.71 8.29,16.01 8.29,13.6 6.65,11.96 U1.90 ; UA11.15 65.88,43.51 v1(65.82,43.57)
  BOTTOM w0.254: v1(10.19,16.71) 10.51,17.03 10.51,31.06 13.24,33.79 42.2,33.79 46.39,37.98 56.42,37.98 57.57,36.84 62.01,36.84 63.28,38.11 63.28,39.38 65.82,41.92 v1(65.82,43.57)
UA11-IN1: length 88.1
  TOP w0.254: UA11.14 66.53,43.39 v1(66.71,43.57) ; v1(10.19,15.56) 8.8,14.17 8.8,13.34 6.92,11.46 U1.91
  BOTTOM w0.254: v1(10.19,15.56) 11.08,16.45 11.08,30.87 13.5,33.28 42.96,33.28 47.02,37.35 56.17,37.35 57.31,36.2 62.26,36.2 63.92,37.85 63.92,39.12 66.71,41.92 v1(66.71,43.57)
UA11-IN2: length 83.6
  TOP w0.254: UA11.7 v1(66.53,37.47) ; v1(11.15,14.55) 7.56,10.96 U1.92
  BOTTOM w0.254: v1(66.53,37.47) 65.64,36.58 64.55,36.58 62.9,34.93 56.8,34.93 55.66,36.08 47.41,36.08 43.6,32.27 14,32.27 12.23,30.49 12.23,15.63 v1(11.15,14.55)
UA11-IN3: length 85.9
  TOP w0.254: UA11.6 65.88,37.95 v1(65.41,37.48) ; U1.7 9.35,6.28 10.32,7.25 10.32,10.61 12.04,12.33 12.04,14.68 v1(11.15,15.56)
  BOTTOM w0.254: v1(11.15,15.56) 11.65,16.07 11.65,30.68 13.75,32.77 43.21,32.77 47.15,36.71 55.91,36.71 57.06,35.57 62.52,35.57 64.17,37.22 65.15,37.22 v1(65.41,37.48)
UB11-IN0: length 69.2
  TOP w0.254: UB11.15 v1(67.78,8.14) ; U1.97 5.95,8.46 6.13,8.64 7.27,8.64 v1(8.04,7.88)
  BOTTOM w0.254: v1(67.78,8.14) 65.37,5.72 56.34,5.72 54.18,3.56 52.74,3.56 52.36,3.94 47.66,3.94 45.5,6.1 27.97,6.1 26.96,5.09 23.15,5.09 21.94,6.29 16.29,6.29 15.72,6.87 9.05,6.87 v1(8.04,7.88)
UB11-IN1: length 71.2
  TOP w0.254: v1(68.74,8.14) 68.43,7.83 UB11.14 ; U1.98 6.94,7.96 v1(7.02,7.88)
  BOTTOM w0.254: v1(68.74,8.14) 65.69,5.09 56.55,5.09 54.39,2.93 52.49,2.93 51.98,3.44 47.28,3.44 45.12,5.6 28.16,5.6 26.2,3.63 25.24,3.63 24.42,4.45 21.94,4.45 20.61,5.79 15.97,5.79 15.4,6.36 8.54,6.36 v1(7.02,7.88)
UB11-IN2: length 69.6
  TOP w0.254: U1.99 6.55,7.46 v1(7.4,6.61) ; v1(68.74,2.17) 68.43,2.48 UB11.7
  BOTTOM w0.254: v1(7.4,6.61) 8.16,5.85 15.15,5.85 15.72,5.28 20.35,5.28 22.58,3.06 26.32,3.06 28.36,5.09 43.98,5.09 46.9,2.17 65.69,2.17 66.33,2.8 68.11,2.8 v1(68.74,2.17)
UB11-IN3: length 68.2
  TOP w0.254: v1(6.38,6.61) 6.03,6.96 U1.100 ; v1(67.78,2.16) UB11.6
  BOTTOM w0.254: v1(67.78,2.16) 66.58,2.16 66.07,1.66 45.37,1.66 42.45,4.58 28.61,4.58 26.58,2.55 22.2,2.55 19.97,4.77 15.4,4.77 14.83,5.34 7.65,5.34 v1(6.38,6.61)
UNNAMED_2_ADM1178_I544_GATE: length 7.8
  TOP w0.254: 17.16,41.09 16.66,40.59 U2.9
  TOP w0.305: Q1.3 17.29,46.37 17.69,45.98 17.69,42.81 17.16,42.28 17.16,41.09
UNNAMED_2_ADM1178_I544_SENSE: length 15.4
  TOP w0.254: U2.2 16.66,44.85 15.53,45.98 15.53,47.38
  TOP w0.508: Q1.6 19.33,48.94 ; Q1.6 18.35,48.38 ; Q1.6 20.3,48.38 ; R6.2 15.4,48.9 ; R6.2 14.51,48.01 ; R6.2 13.75,48.9 ; 15.83,48.38 Q1.1 ; Q1.1 16.81,48.94 ; Q1.1 17.79,48.38 ; 18.35,47.38 Q1.5 20.3,47.38 ; 17.79,47.38 Q1.2 15.83,47.38
UNNAMED_2_ADM1178_I544_TIMER: length 2.1
  TOP w0.254: C11.2 14.64,44.97 15.16,44.44 U2.5
UNNAMED_2_ADM7171_I450_EN: length 9
  TOP w0.254: C104.1 40.37,49.93 U6.8 ; C104.1 40.25,51.02 40.66,51.43 U6.5 ; C104.1 40.64,50.43 U6.7
  TOP w1.016: C104.1 40.25,48.17 E4.2
UNNAMED_2_ADM7171_I450_SENSE: length 2.7
  TOP w0.254: U6.3 46.44,50.93 R97.2 R98.1
UNNAMED_2_ADM7171_I450_SS: length 1.4
  TOP w0.254: C105.2 46.18,51.43 U6.4
UNNAMED_2_ADP1614_I395_CLRES: length 6.3
  TOP w0.254: R12.1 24.29,45 R11.1 25.73,44.33 27.34,44.33 27.85,43.81 U9.9
UNNAMED_2_ADP1614_I395_COMP: length 5.2
  TOP w0.254: U9.1 27.36,39.71 27.09,39.44 27.09,38.74 26.58,38.23 C20.1 25.65,38.2 C110.2
UNNAMED_2_ADP1614_I395_SS: length 1.8
  TOP w0.254: C109.2 25.94,43.31 27.33,43.31 U9.10
UNNAMED_2_ADP1614_I395_SW1: length 7.6
  TOP w0.254: 29.18,44.08 28.86,43.75 U9.7 U9.6 ; U9.6 29.36,44 ; U9.6 29.79,43.29
  TOP w0.762: 30.85,43.95 D4.A ; D4.A 31.58,43.28 ; D4.A 31.58,44.62
  TOP w1.016: 34.58,46.32 L3.2 32.42,45.54
UNNAMED_2_ADP2442_I24_COMP: length 4.2
  TOP w0.254: CC1.2 5.55,49.26 5.51,49.22 4.8,49.22 ; U5.2 5.62,48.39 4.8,49.22 ; 4.8,49.22 CC2.2
UNNAMED_2_ADP2442_I24_FB: length 6.1
  TOP w0.254: RF1.1 10,49.73 RF2.2 7.91,49.73 7.46,49.28 7.46,48.65 7.15,48.33 6.38,48.33 6.12,48.07 U5.1
UNNAMED_2_ADP2442_I24_FREQ: length 4.3
  TOP w0.254: RFREQ.2 3.21,46.87 3.21,45.79 3.4,45.6 U5.5
UNNAMED_2_ADP2442_I24_PGND: length 10.8
  TOP w0.406: 1.52,39.12 2.45,40.05 CC.1
  TOP w0.508: L2.2 1.52,39.12 ; L2.2 0.77,39.83 ; L2.2 0.77,38.41 ; 1.14,42.41 CVCC2.2 1.99,43.31 ; RFILT.2 1.01,41.93 ; RFILT.2 1.01,40.13 ; RFILT.2 1.86,41.03 ; COUT1.2 CC.1
UNNAMED_2_ADP2442_I24_SW: length 4.9
  TOP w0.305: 5.62,43.06 U5.8
  TOP w0.508: L1.1 7.15,38.07 ; L1.1 5.57,37.32 ; L1.1 8.72,37.32
UNNAMED_2_ADP2442_I24_SYNC: length 5.2
  TOP w0.254: U5.6 2.95,45.1 2.7,45.35 2.7,46.36 2.45,46.62 CSS.2 R21.1
UNNAMED_2_ADP7118_I458_EN: length 7.7
  TOP w0.254: U7.4 v1(53.44,52.33)
  TOP w0.305: 53.3,50.41 U7.6
  TOP w0.508: 53.3,50.41 52.06,50.41 C107.1
  TOP w0.762: C107.1 v1(50.83,50.62) 49.77,50.62 D3.C
  BOTTOM w0.254: v1(53.44,52.33) 51.72,50.62 v1(50.83,50.62)
UNNAMED_2_ADP7118_I458_SS: length 1.8
  TOP w0.254: U7.5 52.99,51.06 52.41,51.64 C112.2
UNNAMED_2_ADP7118_I522_SENSE: length 7.7
  TOP w0.305: U3.2 -5.3,11.56 C14.2 -5.95,11.71 U3.1
  TOP w0.508: C15.1 -5.55,9.75 C14.2
  TOP w1.016: C15.1 -5.77,7.4 E3.1
UNNAMED_2_ADR38X_I459_VOUT: length 6.8
  TOP w0.406: 61.25,51.22 C8.2 ; C8.2 61.83,51.77 ; C8.2 60.66,51.77
  TOP w0.508: 61.88,50.73 E2.1 60.94,49.85 ; 62.02,51.82 C10.1 62.71,51.07 ; 60.72,50.07 U4.2 59.9,51.07
UNNAMED_2_CAP_I360_N1: length 1.9
  TOP w0.254: CC1.1 5.55,50.96 5.51,51 RC1.2
UNNAMED_2_CAP_I384_N2: length 4.9
  TOP w0.254: U1.78 2.49,17.96 2.19,17.66 R3.2 C5.2
UNNAMED_2_CAP_I419_N1: length 11
  TOP w0.762: 36.99,41.03 38.19,41.03 ; 36.99,41.03 36.99,41.84 ; 36.99,41.03 35.8,41.03
  TOP w1.016: 33.5,41.66 C30.1 33.4,43.88 ; 33.5,41.66 33.5,43.77 33.4,43.88 ; 33.5,41.66 34.64,41.66 ; 33.4,43.88 D4.C ; D4.C 33.32,43.14 ; D4.C 34.5,43.95
UNNAMED_2_CAP_I439_N1: length 15.4
  TOP w0.254: v1(28.23,39.12) 28.36,39.25 U9.3 ; R11.2 25.35,47.76 27.21,47.76 v1(27.34,47.63)
  TOP w0.305: U9.8 28.36,45.56 C23.1
  BOTTOM w0.254: v1(28.23,39.12) 28.23,46.74 v1(27.34,47.63)
UNNAMED_2_CAP_I486_N1: length 1.9
  TOP w0.254: C110.1 23.95,38.2 R95.2
UNNAMED_2_CAP_I529_N1: length 6.6
  TOP w0.254: 6.85,23.29 6.85,23.44 6.67,23.63 6.67,25.66 Y1.1 ; 6.85,23.29 U1.74 ; 6.85,23.29 C6.1
UNNAMED_2_CAP_I530_N1: length 7.1
  TOP w0.254: Y1.2 3.43,26.27 4.83,24.86 4.83,23.63 4.99,23.47 ; 4.99,23.47 6.35,22.11 U1.75 ; 4.99,23.47 C7.1
UNNAMED_2_CN5P4PSHLD_I378_GND1: length 17.7
  TOP w0.508: -0.98,29.93 C101.2 -1.73,29.22 ; -1.73,30.87 R55.2 ; R55.2 -0.98,31.58 ; R55.2 -0.98,30.16
  BOTTOM w0.254: -7.08,32.27 -7.13,32.21 P1.7 ; -7.08,21.85 -7.13,21.9 P1.6
  BOTTOM w0.508: -4.05,23.64 P1.8 ; P1.8 -5.23,24.63 ; P1.8 -2.87,24.63 ; P1.8 -4.05,25.62 ; P1.9 -2.87,29.48 ; P1.9 -4.05,30.47 ; P1.9 -5.23,29.48 ; P1.9 -4.05,28.49 ; P1.7 -5.59,31.16 ; P1.6 -5.59,22.96
  vias: v1(-2.25,31) v1(-2.25,30.11) v1(-2.25,29.22)
UNNAMED_2_CN5P4PSHLD_I378_N1: length 7.2
  TOP w0.381: -2.51,25.51 -2.76,25.76 P1.1
  TOP w0.762: E1.2 -3.42,22.08 -2.51,22.99 -2.51,25.51
UNNAMED_2_CN6P_I299_N1: length 4.7
  TOP w0.254: R14.2 R50.1 41.69,10.55 41.44,10.29 P3.1
UNNAMED_2_CN6P_I299_N2: length 8.4
  TOP w0.254: R23.2 R52.1 38.39,10.68 38.9,10.17 P3.2
UNNAMED_2_CN6P_I299_N3: length 4.8
  TOP w0.254: R35.2 R51.1 36.86,10.93 36.36,10.42 P3.3
UNNAMED_2_CN6P_I299_N4: length 8.4
  TOP w0.254: R44.2 R53.1 33.82,14.61 33.56,14.36 33.56,9.25 P3.4
UNNAMED_2_DIOLED_I548_N: length 3.5
  TOP w0.254: DS1.C -0.75,3.29 -0.35,3.69 R41.1
UNNAMED_2_DIOLED_I553_N: length 4.3
  TOP w0.254: DS2.C 5.85,2.42 5.6,2.67 4.1,2.67 3.8,2.98 R43.1
UNNAMED_2_DIOLED_I554_N: length 2.8
  TOP w0.254: DS3.C 12.46,3.08 R42.1
UNNAMED_2_ICATSAM3UXXX_I532_ERA: length 22.7
  TOP w0.254: v1(32.67,3.82) 30.01,6.48 30.01,13.6 28.61,14.99 21.75,14.99 21.28,15.46 U1.43
  BOTTOM w0.254: v1(32.67,3.82) 32.67,2.71 R56.2
UNNAMED_2_ICATSAM3UXXX_I532_P_1: length 8.3
  TOP w0.254: P5.1 12.84,27.92 11.72,26.8 11.72,22.36 12.35,21.72 U1.63
UNNAMED_2_ICATSAM3UXXX_I532_P_2: length 5.6
  TOP w0.254: U1.62 12.85,21.86 12.23,22.49 12.23,24.77 12.84,25.38 P4.1
UNNAMED_2_ICATSAM3UXXX_I532_PA1: length 22.5
  TOP w0.254: U1.41 28.12,14.46 29.12,13.47 29.12,11.18 27.47,9.53 27.47,7.44 30.96,3.94 v1(31.02,3.94)
  BOTTOM w0.254: R13.2 31.02,2.99 v1(31.02,3.94)
UNNAMED_2_ICATSAM3UXXX_I532_PB2: length 11.1
  TOP w0.254: U1.64 11.85,21.59 11.21,22.23 11.21,28.84 12.84,30.46 P6.1
UNNAMED_2_RES_I435_N2: length 9.9
  TOP w0.508: 27.64,48.78 R45.2 ; R45.2 28.36,49.52 ; R45.2 29.07,48.78
  TOP w0.762: L3.1 34.58,48.69 ; L3.1 32.42,49.47 ; L3.1 30.26,48.69 ; R54.2 23.03,47.72 ; R54.2 21.23,47.72 ; R54.2 22.13,48.57
UNNAMED_3_AD51X2A_I23_B1: length 19.9
  TOP w0.254: A2.6 51.41,47.19 50.58,46.36 50.58,43.31 48.55,41.28 47.41,41.28 47.15,41.03 47.15,39.76 47.53,39.38 47.53,36.08 48.93,34.68 ; UA9.4 49.83,34.54 49.69,34.68 48.93,34.68 ; 48.93,34.68 48.84,34.59 48.83,34.59 48.29,34.06 48.29,33.15 48.55,32.9 UA9.6
UNNAMED_3_AD51X2A_I23_B2: length 3.3
  TOP w0.254: UA9.7 47.85,32.4 C43.1 47.71,31.9 UA9.8
UNNAMED_3_AD56X3_I308_DIN: length 4.1
  TOP w0.254: 48.17,21.34 48.55,21.72 48.55,22.23 49.13,22.82 49.13,23.88 48.88,24.14 U10.8
UNNAMED_3_AD56X3_I308_SCLK: length 4.8
  TOP w0.254: U10.7 49.19,24.64 49.59,24.24 49.59,21.7 R72.2
UNNAMED_3_AD56X3_I308_VOUTA: length 12.3
  TOP w0.254: U10.1 50.84,23.14 50.5,23.48 50.5,24.98 49.75,25.72 48.87,25.72 46.39,28.2 R74.1
UNNAMED_3_AD56X3_I308_VOUTB: length 3.1
  TOP w0.254: U10.2 53.49,23.64 53.76,23.38 R75.1
UNNAMED_3_AD56X3_I308_VREFIN: length 4.6
  TOP w0.254: C99.2 44.99,21.09 44.99,21.72 45.5,22.23 46.64,22.23 47.55,23.14 U10.10
UNNAMED_3_AD7682_I51_DIN: length 3.8
  TOP w0.254: U11.12 30,27.18 30.39,27.57 31.66,27.57 R78.2
UNNAMED_3_AD7682_I51_IN0: length 2.4
  TOP w0.254: U11.16 27.04,25.52 26.64,25.92 26.64,26.23 26.32,26.55 R69.2
UNNAMED_3_AD7682_I51_IN1: length 2.4
  TOP w0.254: R89.2 25.74,24.79 26.01,24.52 U11.18
UNNAMED_3_AD7682_I51_IN2: length 1.5
  TOP w0.254: U11.7 32.22,24.02 32.35,23.88 32.75,23.88 R86.2
UNNAMED_3_AD7682_I51_IN3: length 1.5
  TOP w0.254: R90.2 32.75,25.15 32.29,25.15 32.16,25.02 U11.9
UNNAMED_3_AD7682_I51_REF: length 2.3
  TOP w0.305: 28.8,21.34 29,21.54 U11.2
  TOP w0.762: 28.8,21.34 C72.2
UNNAMED_3_AD7682_I51_REFIN: length 2.6
  TOP w0.254: C74.2 30.51,20.96 30.13,20.96 29.5,21.6 U11.3
UNNAMED_3_AD7682_I51_SDO: length 2.1
  TOP w0.254: R80.1 29,28.07 U11.14
UNNAMED_3_AD7682_I136_DIN: length 2.5
  TOP w0.254: U12.12 39.78,28.65 R81.2
UNNAMED_3_AD7682_I136_IN0: length 1.5
  TOP w0.254: R87.2 36.09,25.87 36.44,25.52 U12.16
UNNAMED_3_AD7682_I136_IN1: length 1.4
  TOP w0.254: R91.2 36.15,24.39 36.48,24.39 36.61,24.52 U12.18
UNNAMED_3_AD7682_I136_IN2: length 1.7
  TOP w0.254: R88.2 42.83,23.93 41.98,23.93 41.9,24.02 U12.7
UNNAMED_3_AD7682_I136_IN3: length 1.9
  TOP w0.254: U12.9 41.9,25.02 42.03,25.15 42.53,25.15 R92.2
UNNAMED_3_AD7682_I136_REF: length 2.3
  TOP w0.254: U12.2 38.78,21.6 38.71,21.53
  TOP w0.508: 38.71,21.53 38.71,21.15 38.13,20.58 C73.2
UNNAMED_3_AD7682_I136_REFIN: length 2.2
  TOP w0.254: U12.3 39.28,21.6 40.17,20.71
UNNAMED_3_AD7682_I136_SCK: length 2.5
  TOP w0.254: U12.13 39.28,28.66 R82.2
UNNAMED_3_AD7682_I136_SDO: length 2.9
  TOP w0.254: U12.14 38.78,28.02 37.88,28.91 R83.1
UNNAMED_3_AD8018_I5_INV: length 7.1
  TOP w0.508: 60.99,30.36 59.47,30.36 58.84,29.73 R25.1 R26.1 R24.2
UNNAMED_3_AD8018_I5_NINV: length 28
  TOP w0.254: A3.1 v1(47.79,42.97)
  TOP w0.508: v1(61.38,38.11) 62.9,36.58 62.9,29.6 62.39,29.09 A4.3
  BOTTOM w0.508: v1(61.38,38.11) 58.2,38.11 53.33,42.97 v1(47.79,42.97)
UNNAMED_3_AD8018_I5_OUT: length 5.1
  TOP w0.508: R47.1 R46.1 58.39,31.63 A4.1
UNNAMED_3_AD8018_I67_INV: length 4.8
  TOP w0.508: A4.6 68.27,29.09 R39.1 R60.1
UNNAMED_3_AD8018_I67_OUT: length 5.6
  TOP w0.508: R49.1 R57.1 68.68,31.12 67.92,30.36 66.07,30.36
UNNAMED_3_AD8210_I21_INV: length 8.3
  TOP w0.254: 64.93,38.11 65.23,38.4 UA11.5
  TOP w0.508: R30.2 59.91,38.93 UA12.1 62.9,39 63.92,37.98 64.8,37.98 64.93,38.11
UNNAMED_3_AD8210_I21_NINV: length 2.2
  TOP w0.508: R84.2 UA12.8
UNNAMED_3_AD8210_I21_OUT: length 2.1
  TOP w0.254: UA12.5 52.81,42.81 R15.1
UNNAMED_3_ADA46612V2_I229_: length 5.2
  TOP w0.254: 45.56,43.62 45.88,43.3 R20.2 ; 45.56,43.62 45.56,44.02 45.3,44.27 A3.6 ; 45.56,43.62 A3.7
UNNAMED_3_ADA46612V2_I231_: length 8.6
  TOP w0.254: A3.2 49.82,43.62 50.07,43.88 50.07,47.63 50.9,48.46 52.18,48.46 52.36,48.28 A2.5
UNNAMED_3_ADG161XV2_I178_D3: length 55.8
  TOP w0.254: 67.34,37.98 67.18,38.15 UA11.8 ; v1(47.14,44.46) R38.1
  TOP w0.305: R38.1 44.34,45.73 A3.5
  TOP w0.508: 67.34,37.98 67.89,37.43 R29.1 v1(66.84,36.58)
  BOTTOM w0.254: v1(47.14,44.46) 46.77,44.09 46.77,42.81 47.41,42.17 50.33,42.17 51.47,41.03 54.26,41.03 57.82,37.47 61.88,37.47 62.26,37.85 62.26,40.27 64.17,42.17 64.17,44.46 64.93,45.22 69.02,45.22 70.9,43.34 70.9,35.88 69.69,34.68 68.74,34.68 v1(66.84,36.58)
UNNAMED_3_ADG161XV2_I178_S1: length 4.3
  TOP w0.356: UA11.1 64.17,41.55
  TOP w0.508: R48.1 64.17,44.33 64.17,41.55
UNNAMED_3_ADG161XV2_I178_S2: length 4.1
  TOP w0.356: 68.36,41.68 UA11.12
  TOP w0.508: 68.36,41.68 68.36,44.84 R28.1
UNNAMED_3_CAP_I224_N1: length 1.9
  TOP w0.508: C67.1 55.03,28.07 56.55,28.07 R26.2
UNNAMED_3_CAP_I224_N2: length 22.3
  TOP w0.508: C43.2 v1(47.53,34.42) ; C67.2 55.03,29.6 56.55,29.6 R25.2 56.68,31.44 R46.2 R47.2 ; R47.2 56.04,34.36 R84.1 R30.1 ; R47.2 v1(55.15,34.04)
  BOTTOM w0.508: v1(55.15,34.04) 54.26,33.15 48.17,33.15 47.53,33.79 v1(47.53,34.42)
UNNAMED_3_CAP_I242_N2: length 2.3
  TOP w0.254: R76.1 C94.2 45.51,32.44 R74.2
UNNAMED_3_CAP_I243_N2: length 2
  TOP w0.254: R77.1 53.69,18.94 C95.2 53.69,20.84 R75.2
UNNAMED_3_CAP_I280_N1: length 2.1
  TOP w0.508: C102.1 71.28,26.55 R60.2
UNNAMED_4_AD51X2A_I27_A2: length 13.8
  TOP w0.254: 49.19,9.66 49.19,13.2 48.8,13.6 45.75,13.6 44.55,14.8 44.55,15.12 ; 49.19,9.66 48.04,9.66 47.66,9.28 47.66,7.88 47.79,7.75 UB9.6 ; 49.19,9.66 UB9.4
UNNAMED_4_AD51X2A_I27_B2: length 3.2
  TOP w0.254: UB9.8 47.77,6.75 47.53,6.99 47.79,7.25 UB9.7
  TOP w0.508: 47.53,6.99 46.86,6.99 C39.1
UNNAMED_4_AD8018_I52_INV: length 5.1
  TOP w0.508: B4.6 68.14,18.04 R33.1 R58.1
UNNAMED_4_AD8018_I52_OUT: length 5.5
  TOP w0.508: B4.7 68.17,19.31 R65.1 R66.1
UNNAMED_4_AD8018_I62_INV: length 5.9
  TOP w0.508: B4.2 58.96,19.31 R10.1 R34.1 R9.2
UNNAMED_4_AD8018_I62_NINV: length 26.8
  TOP w0.254: v1(45.5,12.33) 46.3,12.33 46.56,12.07 B3.1 ; v1(63.15,13.98) 63.15,17.41 62.52,18.04 B4.3
  BOTTOM w0.254: v1(63.15,13.98) 62.26,13.09 56.17,13.09 54.26,11.18 47.66,11.18 46.52,12.33 v1(45.5,12.33)
UNNAMED_4_AD8018_I62_OUT: length 4.8
  TOP w0.508: B4.1 58.52,20.58 R61.1 R59.1
UNNAMED_4_AD8210_I41_INV: length 8.4
  TOP w0.356: UB11.5 66.96,2.95 66.96,2.93
  TOP w0.508: 66.96,2.93 66.46,2.42 61.95,2.42 R32.2 61.44,5.02 UB12.1
UNNAMED_4_AD8210_I41_NINV: length 2.2
  TOP w0.508: 56.3,2.93 56.3,4.96 UB12.8
UNNAMED_4_AD8210_I41_OUT: length 2.1
  TOP w0.254: UB12.5 56.42,10.8 56.3,10.93
UNNAMED_4_ADA46612V2_I136_: length 6.2
  TOP w0.254: 43.6,15.12 43.6,14.1 43.85,13.85 44.74,13.85 45.63,12.96 46.64,12.96 47.21,12.4 B3.2
UNNAMED_4_ADA46612V2_I138_: length 7.6
  TOP w0.254: B3.6 47.86,15.06 47.53,14.74 v1(47.21,14.74) B3.7 ; R7.2 v1(44.48,13.1)
  BOTTOM w0.254: v1(47.21,14.74) 46.12,14.74 v1(44.48,13.1)
UNNAMED_4_ADG161XV2_I97_D3: length 41.5
  TOP w0.254: B3.5 48.51,15.54 48.74,15.31 R8.1 50.14,14.04 50.83,13.34 55.53,13.34 58.07,10.8 v1(58.07,4.07)
  TOP w0.356: v1(69.76,2.17) 69.08,2.84 UB11.8
  TOP w0.508: R31.1 73.69,5.25 73.69,3.06 72.68,2.04 69.88,2.04 v1(69.76,2.17)
  BOTTOM w0.254: v1(58.07,4.07) 59.22,2.93 65.57,2.93 65.95,3.31 68.61,3.31 v1(69.76,2.17)
UNNAMED_4_ADG161XV2_I97_S1: length 3.9
  TOP w0.356: 65.95,6.25 UB11.1
  TOP w0.508: R64.1 65.95,9.02 65.95,6.25
UNNAMED_4_ADG161XV2_I97_S2: length 4
  TOP w0.356: UB11.12 70.39,6.37
  TOP w0.508: 70.39,6.37 70.39,8.9 R63.1
UNNAMED_4_CAP_I135_N1: length 1.5
  TOP w0.508: C84.1 R34.2
UNNAMED_4_CAP_I135_N2: length 53
  TOP w0.508: R10.2 57.06,18.68 C84.2 55.79,20.01 R61.2 R59.2 56.49,23.18 57.57,24.26 59.47,24.26 64.17,19.57 64.17,13.98 59.09,8.9 59.09,3.37 R32.1 R85.1 57.57,2.29 57.06,1.79 46.9,1.79 46.39,2.29 46.39,5.51 C39.2
UNNAMED_4_CAP_I157_N1: length 1.9
  TOP w0.508: R58.2 71.92,15.25 C57.1
UNNAMED_4_DIO6PV2_I110_AC1: length 2.3
  TOP w0.381: 76.11,43.76 D2.6
  TOP w0.508: 76.11,43.76 76.62,43.25 76.62,42.9 R70.2
UNNAMED_4_DIO6PV2_I110_AC2: length 2
  TOP w0.381: 74.39,45.66 D2.3
  TOP w0.508: R71.2 73.41,45.66 74.39,45.66
UNNAMED_4_DIO6PV2_I179_AC1: length 1.9
  TOP w0.406: D11.6 73.96,11.48
  TOP w0.508: 73.96,11.48 R67.2
UNNAMED_4_DIO6PV2_I179_AC2: length 2.1
  TOP w0.406: R68.2 76.26,9.47 D11.3
VSENSE-A: length 53.9
  TOP w0.254: R69.1 v1(24.88,27.31) 24.88,30.06 25.43,30.61 33.56,30.61 35.16,29.01 R91.1 ; R62.1 45.04,40.53 C42.2 45.13,40.6 R20.1 45.88,39.5 46.52,38.87 46.52,36.2 45.75,35.44 44.87,35.44 44.61,35.19 v1(44.61,31.76)
  BOTTOM w0.254: v1(24.88,27.31) 26.51,27.31 27.02,26.8 29.5,26.8 31.66,28.96 32.8,28.96 35.59,31.76 v1(44.61,31.76)
VSENSE-B: length 63.2
  TOP w0.254: v1(32.1,13.41) 27.21,18.3 25.05,18.3 22.39,20.96 22.39,24.14 23.08,24.84 24.43,24.84 R89.1 24.16,25.99 24.16,30.23 25.05,31.12 33.82,31.12 35.98,28.96 R87.1 ; v1(45.5,11.44) 45.25,11.18 44.74,11.18 R7.1 C26.2 43.85,9.15 43.6,8.9 43.6,6.64 R27.1
  BOTTOM w0.254: v1(45.5,11.44) 44.87,12.07 44.48,12.07 43.85,12.71 43.85,13.41 42.39,14.87 37.69,14.87 35.91,13.09 34.45,13.09 34.13,13.41 v1(32.1,13.41)
VSETPOINT-A: length 12.4
  TOP w0.254: R76.2 46.38,34.73 C96.1 46.39,35.31 47.02,35.95 47.02,39.12 46.64,39.5 46.64,43.06 47.86,44.27 A3.3
VSETPOINT-B: length 13.4
  TOP w0.254: B3.3 47.86,12.76 v1(47.66,12.96) ; R77.2 52.82,18.05 C97.1 v1(52.81,14.1)
  BOTTOM w0.254: v1(52.81,14.1) 51.72,14.1 49.44,11.82 47.91,11.82 47.66,12.07 v1(47.66,12.96)
VUSB: length 13.6
  TOP w0.254: v1(16.93,45.47) 17.16,45.24 U2.1
  TOP w0.305: U3.4 -4.65,15.74 -4.92,16.01 -5.95,16.01 U3.6
  TOP w0.508: R6.1 15.22,50.17 ; R6.1 14.51,50.92 ; R6.1 13.8,50.17
  TOP w0.762: -5.95,16.01 -5.95,16.5 C9.2 -5.43,18.64 C12.1 -5.26,19.29 -4.89,19.65 E1.1 v1(-5.93,20.58) -6.38,20.14 v1(-6.38,19.82)
  vias: v1(15.66,50.81) v1(15.66,50.05) v1(16.42,50.81) v1(16.42,50.05)

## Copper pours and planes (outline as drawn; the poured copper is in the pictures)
1V8 on TOP: 17.62,21.98 22.39,21.98 22.39,23.88 20.23,23.88 19.85,23.5 17.62,23.5
1V8 on L3_VDD: 10.13,2.55 10.13,13.02 2.51,13.02 2.51,15.82 7.91,15.82 7.91,22.93 10.26,22.93 10.26,21.41 13.94,21.41 13.94,22.93 15.59,22.93 15.59,21.41 19.02,21.41 19.02,23.69 21.56,23.69 21.56,11.25 22.7,11.25 22.7,4.9 15.66,4.9 15.66,2.55
2V5 on TOP: 69.12,49.41 69.12,53.09 66.2,53.09 66.2,50.68 63.66,50.68 62.9,49.92 62.9,48.52 60.23,48.52 60.23,46.62 62.77,46.62 63.92,47.76 63.92,49.41
2V5 on L3_VDD: 52.49,0.85 52.49,6.23 57.76,6.23 57.76,10.68 69.5,10.68 69.5,5.91 74.4,5.91 77.89,9.4 77.89,24.01 76.49,24.01 76.49,44.97 69.32,44.97 65.69,48.59 65.69,53.3 77.22,53.3 79.43,51.09 79.43,3.06 77.22,0.85
2V5 on L3_VDD: 57.44,23.69 57.44,38.93 52.36,38.93 52.36,41.16 57.44,41.16 57.44,48.14 61.57,48.14 61.57,33.85 65.06,33.85 65.06,23.69
3V3 on TOP: -4.41,6.48 -1.49,6.48 -1.49,8.14 -4.41,8.14
3V3 on L3_VDD: 18.7,0.85 16.29,0.85 16.29,4.26 23.34,4.26 23.34,11.88 22.2,11.88 22.2,24.33 18.39,24.33 18.39,22.04 16.23,22.04 16.23,23.57 13.31,23.57 13.31,22.04 10.89,22.04 10.89,23.57 7.27,23.57 7.27,16.45 1.88,16.45 1.88,12.39 9.5,12.39 9.5,1.91 1.81,1.91 0.8,2.93 0.29,2.93 0.29,0.85 -4.79,0.85 -7,3.06 -7,17.34 0.61,17.34 0.61,25.6 5.37,25.6 5.37,37.03 39.02,37.03 39.02,34.81 52.68,34.81 52.68,28.46 49.95,28.46 49.95,30.36 38.52,30.36 38.52,26.55 33.44,26.55 33.44,4.33 45.81,4.33 46.13,4.01 49.25,4.01 49.25,10.68 53.12,10.68 53.12,9.28 51.85,8.01 51.85,0.85 18.7,0.85
4V5 on TOP: 11.59,40.9 11.59,38.11 14.13,38.11 14.13,40.9
4V5 on L3_VDD: 5.37,37.66 5.37,41.79 15.21,41.79 15.21,44.01 18.7,44.01 18.7,53.3 23.78,53.3 23.78,37.66
4V5_U5 on TOP: 11.59,44.46 11.59,41.66 14.13,41.66 14.13,44.46
4V5_U5 on TOP: 8.8,41.54 6.38,41.54 6,41.92 6,44.46 6.26,44.46 7.02,43.7 8.8,43.7
4V5_U5 on L3_VDD: 3.78,42.43 3.78,49.09 14.58,49.09 14.58,42.43
5V0 on TOP: 55.41,51.32 55.41,49.79 55.79,49.41 55.79,47.25 58.58,47.25 58.58,50.81 57.06,50.81 56.55,51.32
5V0 on BOTTOM: 55.79,49.54 55.79,47.25 57.44,47.25 57.44,49.54
5V0 on L3_VDD: 46.39,4.64 46.08,4.96 34.07,4.96 34.07,25.92 39.15,25.92 39.15,29.73 49.31,29.73 49.31,27.82 53.31,27.82 53.31,35.44 46.01,35.44 46.01,43.56 50.58,48.14 56.8,48.14 56.8,41.79 51.72,41.79 51.72,38.3 56.8,38.3 56.8,23.69 47.6,23.69 47.6,17.66 69.37,17.66 73.63,13.4 73.63,11.31 57.12,11.31 57.12,6.87 52.49,6.87 52.49,7.75 53.76,9.02 53.76,11.31 48.61,11.31 48.61,4.64
6V0 on TOP: 40.8,43.19 40.8,41.28 43.21,41.28 43.21,43.19
6V0 on TOP: 65.69,31.38 67.73,31.38 67.73,35.69 65.69,35.69
6V0 on TOP: 40.8,37.35 40.8,35.69 43.09,35.69 43.09,37.35
6V0 on TOP: 44.74,47.38 44.74,50.68 46.01,50.68 46.26,50.43 46.26,47.38
6V0 on L3_VDD: 70.14,6.55 70.14,10.68 74.27,10.68 74.27,13.66 69.63,18.3 48.23,18.3 48.23,23.06 65.69,23.06 65.69,34.49 62.2,34.49 62.2,48.78 50.32,48.78 45.37,43.83 45.37,35.44 39.66,35.44 39.66,53.3 65.06,53.3 65.06,48.33 69.05,44.33 75.85,44.33 75.85,23.38 77.25,23.38 77.25,9.66 74.13,6.55
6V5 on TOP: 33.56,39.76 33.38,39.68 33.31,39.5 33.31,32.77 39.4,32.77 40.42,33.79 40.42,46.74 39.4,46.74 39.4,35.31 39.02,34.93 36.23,34.93 36.04,35.12 36.23,35.31 38.26,35.31 38.71,35.5 38.9,35.95 38.9,39.38 38.78,39.65 38.52,39.76
-1V0 on TOP: 40.8,38.11 42.07,38.11 42.45,37.73 43.21,37.73 43.21,39.38 42.71,39.89 40.8,39.89
-1V0 on TOP: 40.8,43.7 43.09,43.7 43.21,43.82 43.21,45.6 41.31,45.6 40.8,45.09
-1V0 on TOP: -5.55,43.19 -5.55,40.27 -3.01,40.27 -3.01,43.19
-1V0 on TOP: 65.31,32.77 63.53,32.77 63.53,36.2 65.31,36.2
-1V0 on BOTTOM: 63.53,6.87 63.03,7.37 63.03,10.8 63.53,11.31 65.19,11.31 65.57,11.69 65.57,12.71 63.66,14.61 51.34,14.61 49.31,12.58 48.29,12.58 47.79,13.09 47.79,16.01 46.77,17.03 46.77,19.57 48.04,20.84 51.22,20.84 55.03,24.65 55.03,33.41 62.26,33.41 64.17,35.31 68.49,35.31 69,34.81 69.63,34.81 70.9,36.08 70.9,42.43 69,44.33 64.68,44.33 64.68,41.79 55.41,41.79 53.37,43.82 47.41,43.82 47.41,42.93 49.56,40.77 49.56,39 44.23,39 43.72,38.49 41.06,38.49 41.06,48.78 33.44,48.78 32.8,49.41 20.74,49.41 19.47,48.14 19.47,43.7 16.93,41.16 6.13,41.16 3.59,38.62 -7,38.62 -7,50.5 -4.21,53.3 77.22,53.3 79.43,51.09 79.43,21.37 77.25,19.18 77.25,13.09 74.2,10.04 69,10.04 65.82,6.87 ; 5 cut-outs
-1V0_U5 on TOP: -6.95,35.57 -6.95,51.06 -4.79,53.22 12.99,53.22 12.99,47.25 7.91,47.25 7.91,48.78 10.58,48.78 10.7,48.9 10.7,50.3 9.05,50.3 9.05,51.7 4.1,51.7 4.1,48.27 2.32,48.27 2.32,49.16 0.8,49.16 0.8,47.51 -2.51,47.51 -2.51,45.73 0.92,45.73 0.92,44.58 0.16,44.58 -0.22,44.2 -0.22,35.57 ; 2 cut-outs
GND on TOP: 25.94,44.97 27.21,44.97 27.21,46.87 26.96,47.12 25.94,47.12 25.69,46.87 25.69,45.22
GND on TOP: outline of 106 points within -7,4.26 3.59,20.07
